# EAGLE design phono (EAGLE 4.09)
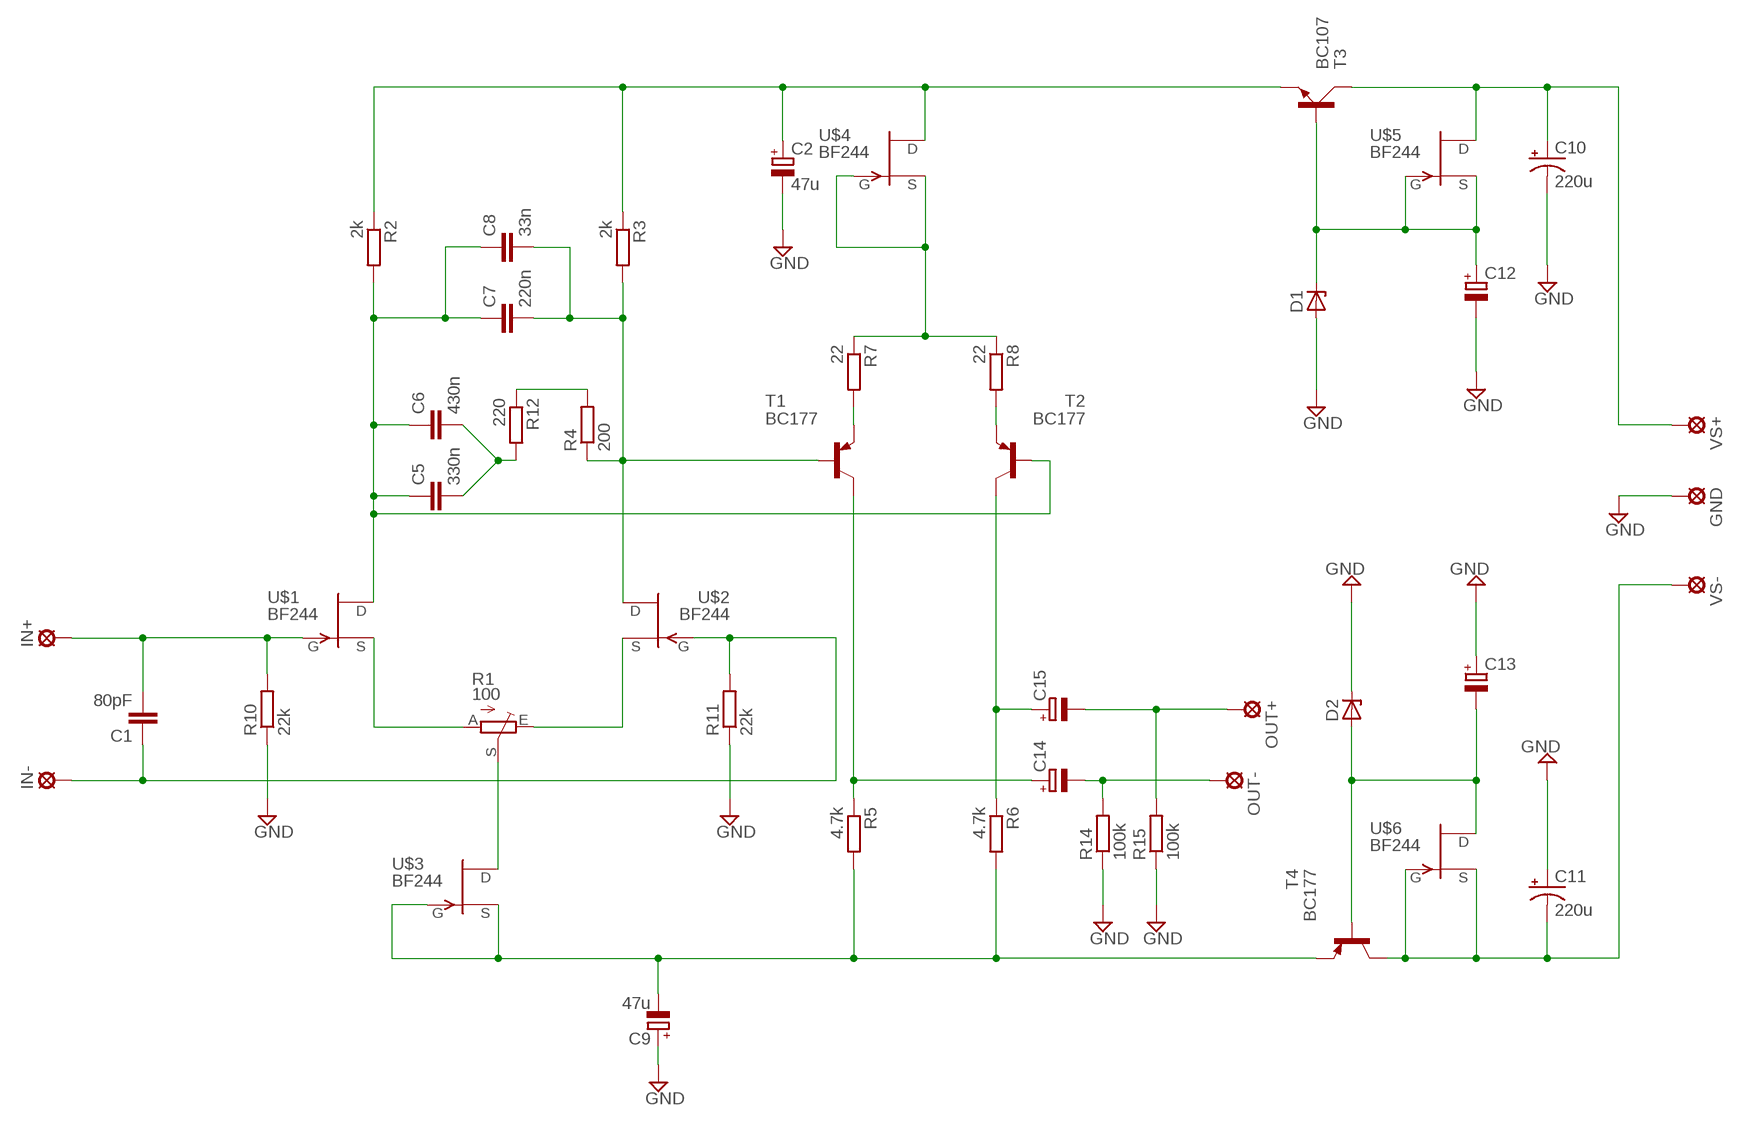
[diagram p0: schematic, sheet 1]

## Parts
C1  80pF  C-EU050-025X075  [C050-025X075]
C2  47u  CPOL-EUE3.5-10  [E3,5-10]
C5  330n  C10/4  [C10B4]
C6  430n  C10/4  [C10B4]
C7  220n  C10/4  [C10B4]
C8  33n  C10/4  [C10B4]
C9  47u  CPOL-EUE3.5-10  [E3,5-10]
C10  220u  CPOL-USE10-20  [EB20D]
C11  220u  CPOL-USE10-20  [EB20D]
C12  CPOL-EUE5-8.5  [E5-8,5]
C13  CPOL-EUE5-8.5  [E5-8,5]
C14  CPOL-EUE5-9VAXIAL  [E5R]
C15  CPOL-EUE5-9VAXIAL  [E5R]
D1  ZENER-DIODEZD-10  [ZDIO-10]
D2  ZENER-DIODEZD-10  [ZDIO-10]
GND  LSP10  [LSP10]
IN+  LSP10  [LSP10]
IN-  LSP10  [LSP10]
OUT+  LSP10  [LSP10]
OUT-  LSP10  [LSP10]
R1  100  TRIM_EU-B64Y  [B64Y]
R2  2k  R-EU_0207/15  [0207/15]
R3  2k  R-EU_0207/15  [0207/15]
R4  200  R-EU_0207/15  [0207/15]
R5  4.7k  R-EU_0207/15  [0207/15]
R6  4.7k  R-EU_0207/15  [0207/15]
R7  22  R-EU_0207/15  [0207/15]
R8  22  R-EU_0207/15  [0207/15]
R10  22k  R-EU_0207/15  [0207/15]
R11  22k  R-EU_0207/15  [0207/15]
R12  220  R-EU_0207/15  [0207/15]
R14  100k  R-EU_0207/15  [0207/15]
R15  100k  R-EU_0207/15  [0207/15]
T1  BC177  [TO18]
T2  BC177  [TO18]
T3  BC107  [TO18A]
T4  BC177  [TO18]
U$1  BF244  [TO92-]
U$2  BF244  [TO92-]
U$3  BF244  [TO92-]
U$4  BF244  [TO92-]
U$5  BF244  [TO92-]
U$6  BF244  [TO92-]
VS+  LSP10  [LSP10]
VS-  LSP10  [LSP10]

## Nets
GND: C2.- C9.+ C10.- C11.+ C12.- C13.+ D1.A D2.C GND.MP R10.1 R11.1 R14.1 R15.1
N$1: R1.S U$3.3(D)
N$3: R4.2 R12.1
N$4: R1.A U$1.1(S)
N$5: R1.E U$2.1(S)
N$6: R7.2 T1.1(E)
N$7: R8.2 T2.1(E)
N$8: C2.+ R2.1 R3.1 T3.E U$4.3(D)
N$10: C14.+ R5.1 T1.3(C)
N$11: C15.+ R6.1 T2.3(C)
N$12: C5.1 C6.1 C7.1 C8.1 R2.2 T2.2(B) U$1.3(D)
N$14: R7.1 R8.1 U$4.1(S) U$4.2(G)
N$15: C5.2 C6.2 R12.2
N$16: C9.- R5.2 R6.2 T4.1(E) U$3.1(S) U$3.2(G)
N$17: C1.1 IN-.MP R11.2 U$2.2(G)
N$18: C12.+ D1.C T3.B U$5.1(S) U$5.2(G)
N$19: C1.2 IN+.MP R10.2 U$1.2(G)
N$22: C7.2 C8.2 R3.2 R4.1 T1.2(B) U$2.3(D)
N$24: C14.- OUT-.MP R14.2
N$25: C15.- OUT+.MP R15.2
N$26: C13.- D2.A T4.2(B) U$6.3(D)
N$28: C11.- T4.3(C) U$6.1(S) U$6.2(G) VS-.MP
N$34: C10.+ T3.C U$5.3(D) VS+.MP

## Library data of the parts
C1 = rcl:C-EU: CAPACITOR, European symbol
C2 C9 C12-C15 = rcl:CPOL-EU: POLARIZED CAPACITOR, European symbol
C5-C8 = capacitor-wima:C: CAPACITOR
C10 C11 = rcl:CPOL-US: POLARIZED CAPACITOR, American symbol
D1 D2 = diode:ZENER-DIODE: Z-Diode
GND IN+ IN- OUT+ OUT- VS+ VS- = solpad:LSP10: SOLDER PAD
R1 = pot:TRIM_EU-: POTENTIOMETER
R2-R8 R10-R12 R14 R15 = rcl:R-EU_: RESISTOR, European symbol
T1 T2 T4 = transistor-pnp:BC177*: PNP Transistor
T3 = transistor-small-signal:BC107: NPN TRANSISTOR
U$1-U$6 = transistor-fet:BF244: RF amplifier up to 450MHz

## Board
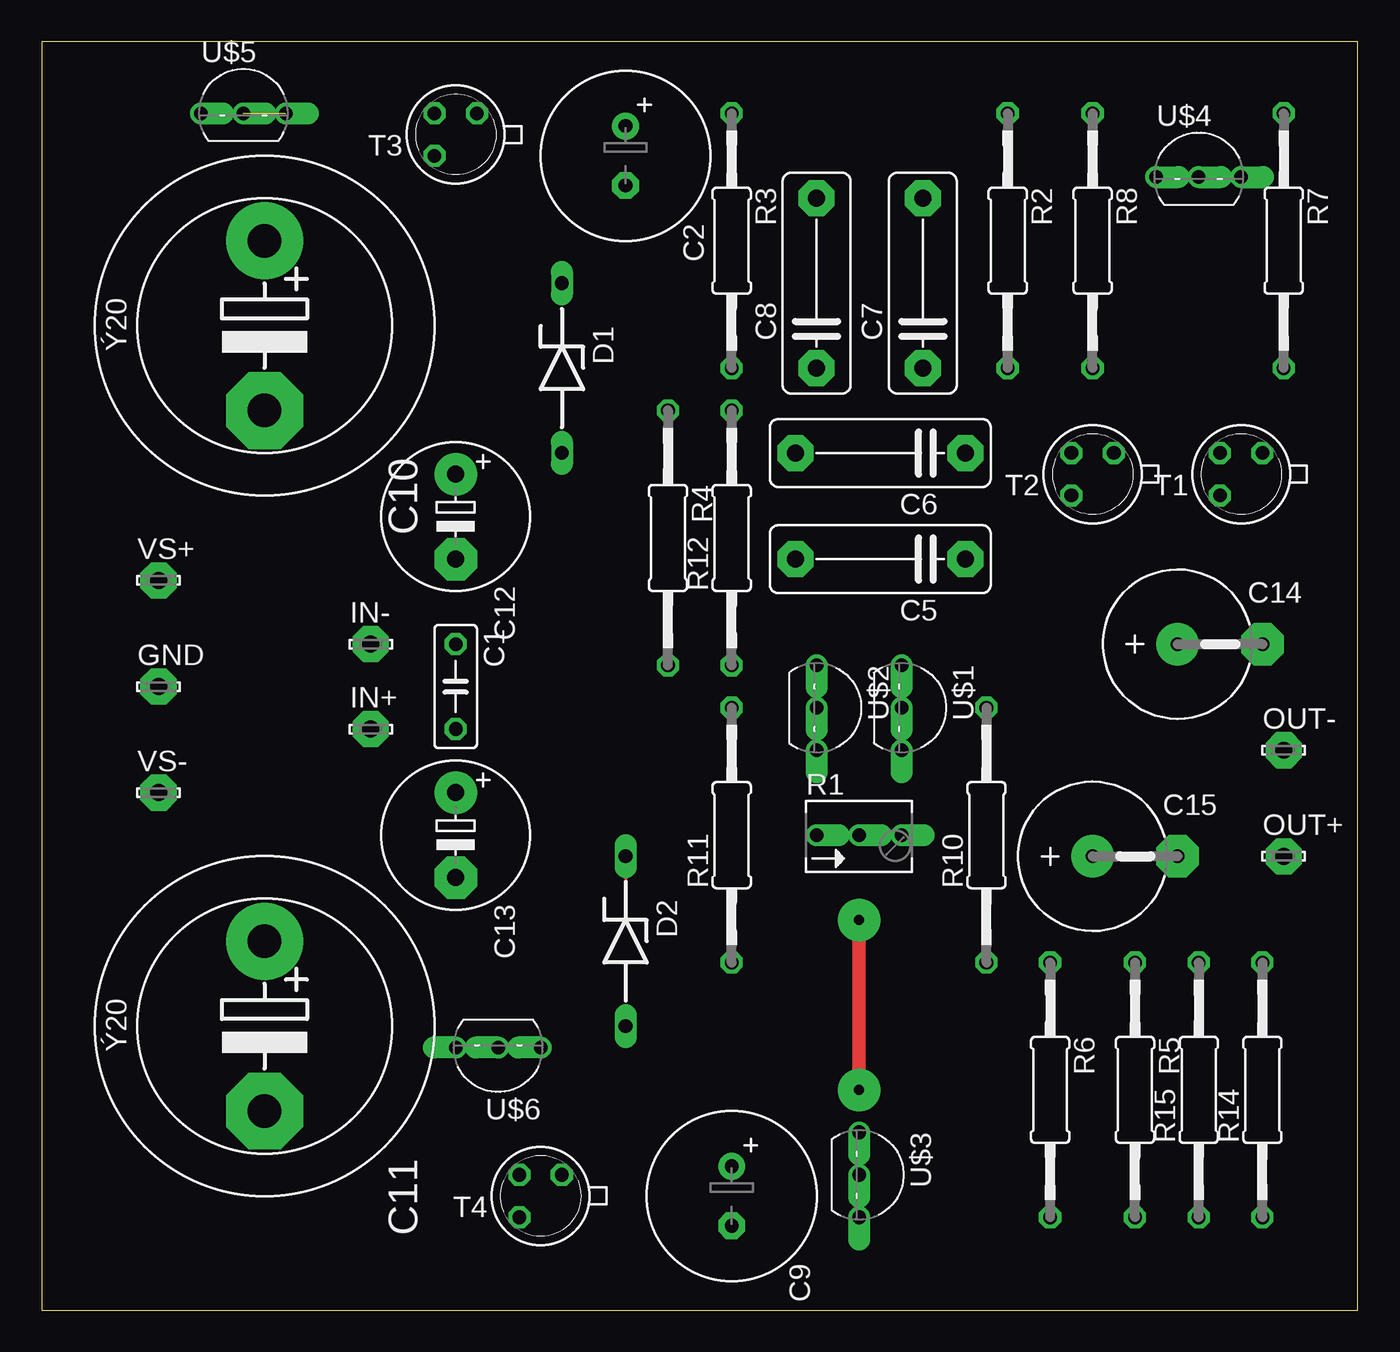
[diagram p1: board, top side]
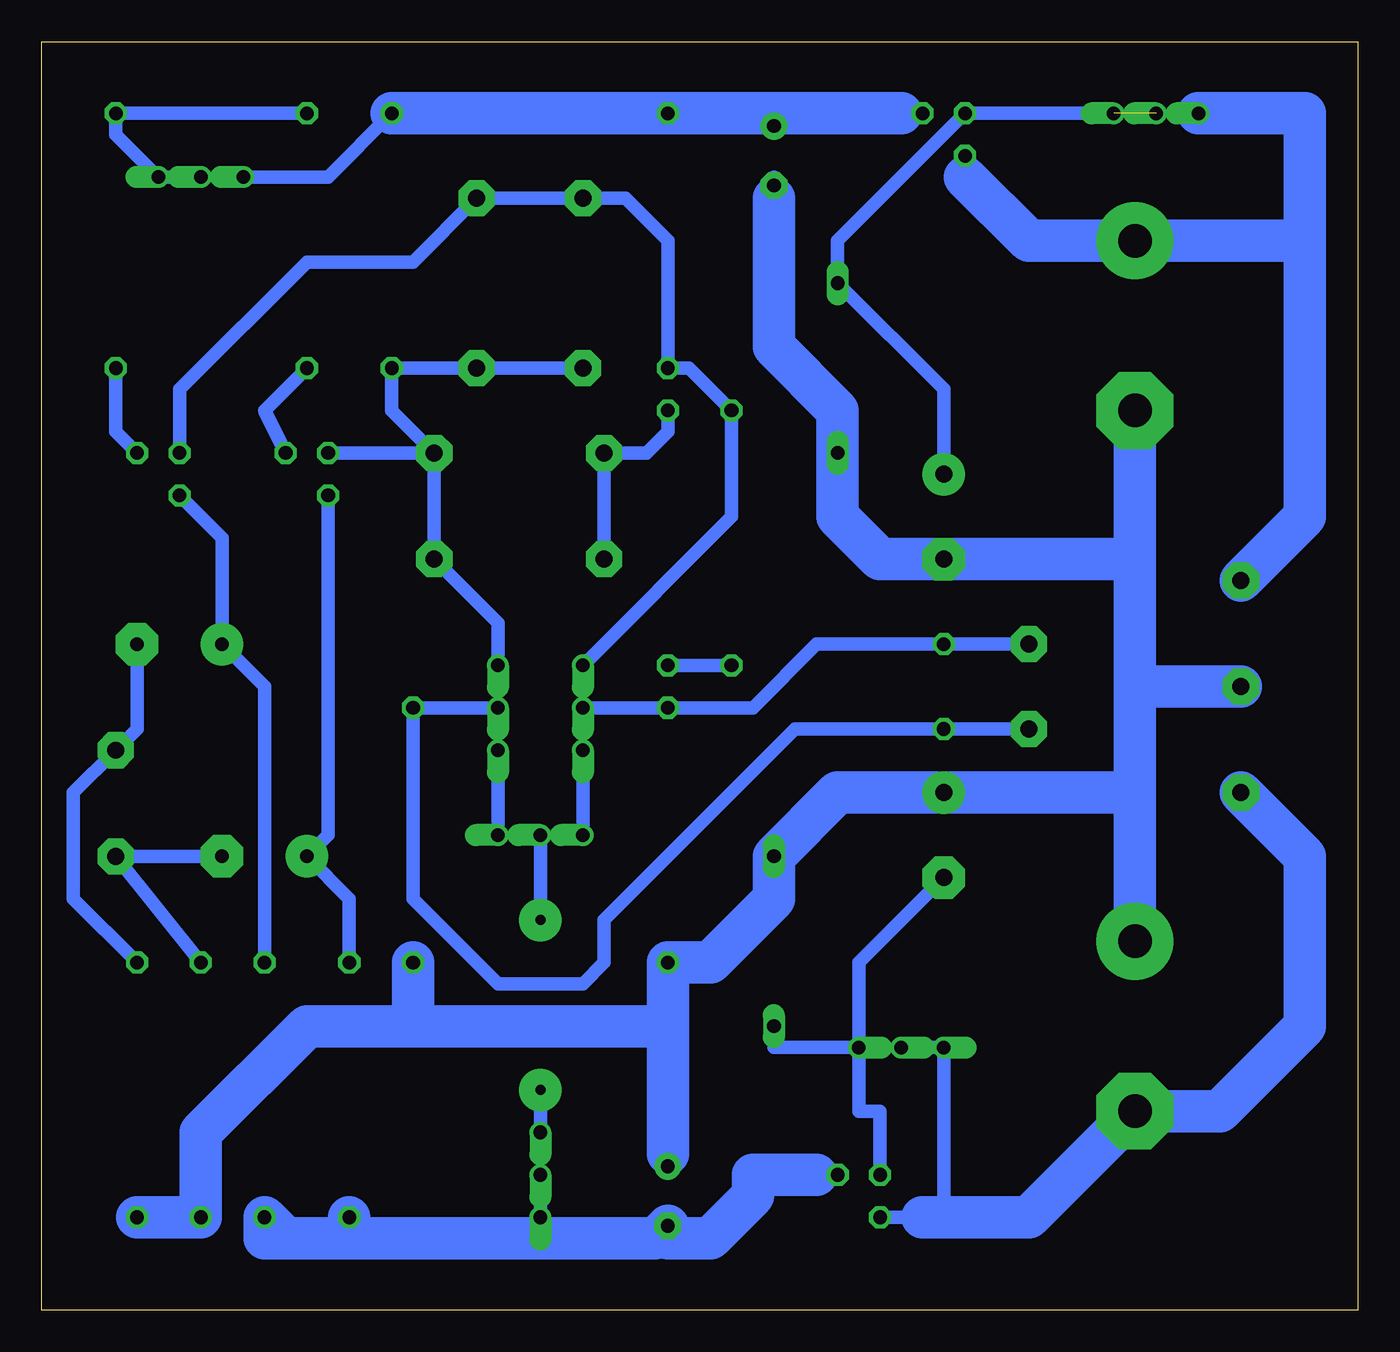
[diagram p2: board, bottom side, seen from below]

Size 78.72 x 75.87 mm. Coordinates in mm from the lower left corner, seen from the top.
Outline: 0,0 78.72,0 78.72,75.87 0,75.87 0,0
Copper layers used: Top, Bottom

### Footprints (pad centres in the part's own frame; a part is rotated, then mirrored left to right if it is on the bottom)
C050-025X075 = drill 0.813 octagon: 1 -2.54,0; 2 2.54,0
E3,5-10 = drill 0.813 pad 1.6 round: + -1.778,0 | drill 0.813 pad 1.6 octagon: - 1.778,0
C10B4 = drill 1.016 pad 2.159 octagon: 1 -5.08,0; 2 5.08,0
EB20D = drill 2.007 pad 4.597 round: + -5.08,0 | drill 2.007 pad 4.597 octagon: - 5.08,0
E5-8,5 = drill 1.016 pad 2.54 round: + -2.54,0 | drill 1.016 pad 2.54 octagon: - 2.54,0
E5R = drill 0.813 pad 2.54 round: + -2.54,0 | drill 0.813 pad 2.54 octagon: - 2.54,0
ZDIO-10 = drill 0.813 long: A 5.08,0; C -5.08,0
LSP10 = drill 1.016 pad 2.159 octagon: MP 0,0
B64Y = drill 0.813 offset: A 2.54,0; E -2.54,0; S 0,0
0207/15 = drill 0.813 octagon: 1 -7.62,0; 2 7.62,0
TO18 = drill 0.813 octagon: 1 -1.27,-1.27; 2 1.27,-1.27; 3 1.27,1.27
TO18A = drill 0.813 octagon: B 1.27,-1.27; C 1.27,1.27; E -1.27,-1.27
TO92- = drill 0.813 offset: 1 2.54,0; 2 0,0; 3 -2.54,0

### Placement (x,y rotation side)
C1  24.76,37.3 270 top
C2  34.92,69.05 270 top
C5  50.16,44.92 180 top
C6  50.16,51.27 180 top
C7  52.7,61.43 90 top
C8  46.35,61.43 90 top
C9  41.27,6.82 270 top
C10  13.33,58.89 270 top
C11  13.33,16.98 270 top
C12  24.76,47.46 270 top
C13  24.76,28.41 270 top
C14  70.48,39.84 0 top
C15  65.4,27.14 0 top
D1  31.11,56.35 270 top
D2  34.92,22.06 270 top
GND  6.98,37.3 0 top
IN+  19.68,34.76 0 top
IN-  19.68,39.84 0 top
OUT+  74.29,27.14 0 top
OUT-  74.29,33.49 0 top
R1  48.89,28.41 0 top
R2  57.78,63.97 270 top
R3  41.27,63.97 270 top
R4  37.46,46.19 270 top
R5  65.4,13.17 270 top
R6  60.32,13.17 270 top
R7  74.29,63.97 270 top
R8  62.86,63.97 270 top
R10  56.51,28.41 90 top
R11  41.27,28.41 90 top
R12  41.27,46.19 90 top
R14  73.02,13.17 90 top
R15  69.21,13.17 90 top
T1  71.75,50 180 top
T2  62.86,50 180 top
T3  24.76,70.32 180 top
T4  29.84,6.82 180 top
U$1  51.43,36.03 270 top
U$2  46.35,36.03 270 top
U$3  48.89,8.09 270 top
U$4  69.21,67.78 0 top
U$5  12.06,71.59 0 top
U$6  27.3,15.71 180 top
VS+  6.98,43.65 0 top
VS-  6.98,30.95 0 top

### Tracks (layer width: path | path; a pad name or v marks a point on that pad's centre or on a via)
GND
  Top 0.254: D2.C 34.92,25.87
  Bottom 0.813: 34.92,67.78 C2.- 34.92,66.51 | 41.27,9.36 C9.+
  Bottom 2.54: GND.MP 13.33,37.3 13.33,30.95 | C11.+ 13.33,30.95 | 13.33,30.95 13.33,44.92 | 13.33,44.92 C10.- | 34.92,66.51 34.92,57.62 31.11,53.81 D1.A 31.11,47.46 28.57,44.92 C12.- 13.33,44.92 | 41.27,16.98 41.27,9.36 | 41.27,16.98 R11.1 38.73,20.79 34.92,24.6 D2.C 31.11,30.95 C13.+ 13.33,30.95 | R14.1 R15.1 69.21,10.63 62.86,16.98 56.51,16.98 | 41.27,16.98 56.51,16.98 | 56.51,16.98 R10.1
N$1  (via drill 0.61 pad 2.54)
  Top 0.813: v48.89,13.17 v48.89,23.33
  Bottom 0.813: U$3.3 v48.89,13.17 | v48.89,23.33 R1.S
N$2  (via drill 0.61 pad 2.54)
  other vias: 48.89,23.33
N$3
  Bottom 0.813: R4.2 R12.1
N$4
  Bottom 0.813: R1.A U$1.1
N$5
  Bottom 0.813: R1.E U$2.1
N$6
  Bottom 0.813: T1.1 74.29,52.54 R7.2
N$7
  Bottom 0.813: T2.1 65.4,53.81 R8.2
N$8
  Bottom 0.813: T3.E 27.3,71.59 | 34.92,71.59 C2.+ | R2.1 61.59,67.78 U$4.3
  Bottom 2.54: R2.1 R3.1 34.92,71.59 27.3,71.59
N$9  (via drill 0.61 pad 2.54)
  other vias: 48.89,13.17
N$10
  Bottom 0.813: T1.3 67.94,46.19 C14.+ 65.4,37.3 R5.1
N$11
  Bottom 0.813: R6.1 60.32,24.6 C15.+ 61.59,28.41 T2.3
N$12
  Bottom 0.813: C8.1 C7.1 R2.2 57.78,53.81 C6.1 | U$1.3 51.43,41.11 C5.1 C6.1 | C6.1 T2.2
N$14
  Bottom 0.813: U$4.2 U$4.1 74.29,70.32 R7.1 R8.1
N$15
  Bottom 0.813: C5.2 C6.2 42.54,51.27 41.27,52.54 R12.2
N$16
  Bottom 0.813: 41.27,5.55 C9.- 41.27,4.28 | 48.89,4.28 U$3.1 U$3.2 | 32.38,8.09 T4.1
  Bottom 2.54: 41.27,4.28 38.73,4.28 36.19,6.82 36.19,8.09 32.38,8.09 | C9.- 42.03,4.28 48.89,4.28 60.32,4.28 | 64.13,4.28 R5.2 65.4,4.28 64.13,4.28 | 60.32,4.28 64.13,4.28 | 60.32,4.28 R6.2
N$17
  Bottom 0.813: IN-.MP C1.1 32.38,39.84 36.19,36.03 R11.2 U$2.2
N$18  (1 unrouted)
  Bottom 0.813: C12.+ 24.76,55.08 D1.C 31.11,63.97 T3.B U$5.1
N$19
  Bottom 0.813: R10.2 U$1.2 R10.2 | R10.2 56.51,24.6 51.43,19.52 46.35,19.52 45.08,20.79 45.08,23.33 33.65,34.76 C1.2 IN+.MP
N$22
  Bottom 0.813: U$2.3 37.46,47.46 R4.1 40,56.35 R3.2 41.27,63.97 43.81,66.51 C8.2 C7.2 56.51,62.7 62.86,62.7 70.48,55.08 T1.2
N$24
  Bottom 0.813: R14.2 76.83,24.6 76.83,30.95 OUT-.MP 73.02,34.76 C14.-
N$25
  Bottom 0.813: C15.- OUT+.MP R15.2
N$26
  Bottom 0.813: T4.2 28.57,11.9 29.84,11.9 U$6.3 | U$6.3 34.92,15.71 D2.A | U$6.3 29.84,20.79 C13.-
N$28
  Bottom 0.813: 26.03,5.55 T4.3 24.76,5.55 U$6.1 U$6.2
  Bottom 2.54: VS-.MP 3.17,27.14 3.17,16.98 8.25,11.9 C11.- 19.68,5.55 24.76,5.55 26.03,5.55
N$34
  Bottom 0.813: 23.49,67.78 T3.C
  Bottom 2.54: VS+.MP 3.17,47.46 3.17,63.97 | 3.17,63.97 3.17,69.05 | 3.17,69.05 3.17,70.32 | 3.17,63.97 C10.+ 19.68,63.97 23.49,67.78 | U$5.3 3.17,71.59 3.17,69.05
